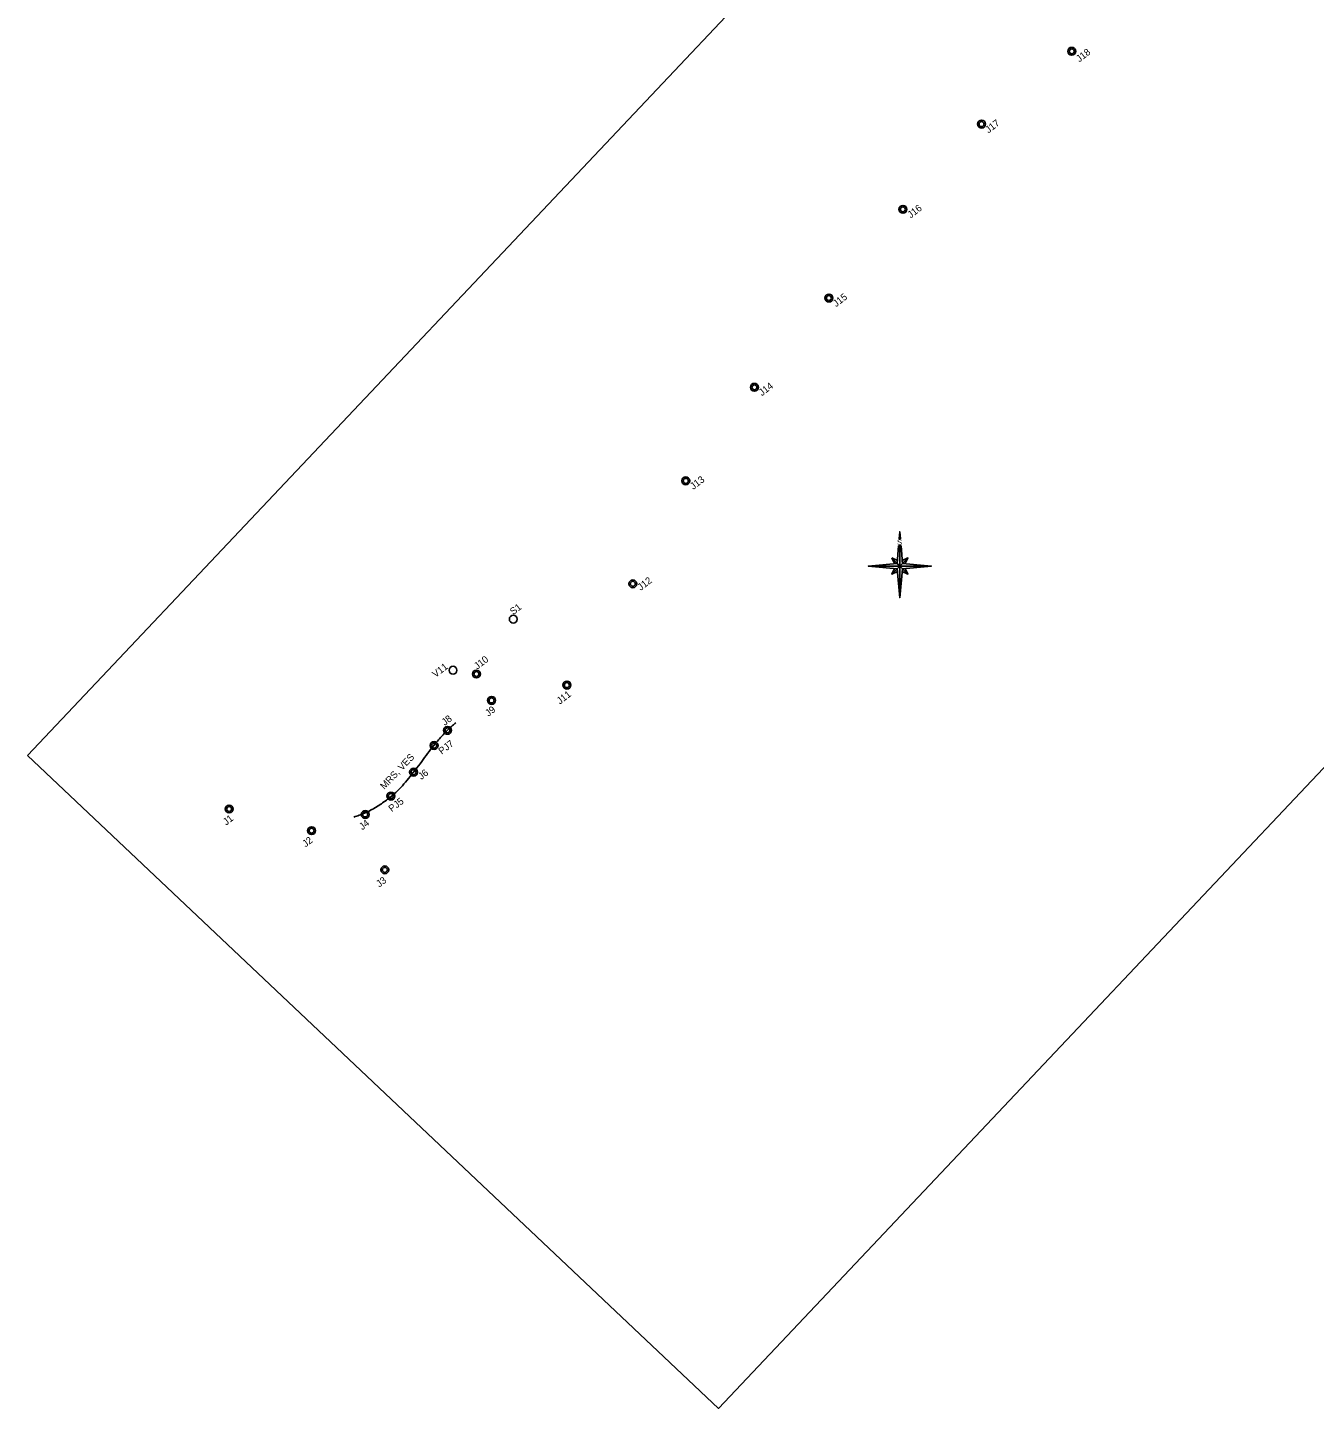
# Model space of a CAD drawing. Extents: x -705558 to -700007, y -1016452 to -1010613.
# Drawn here: x -705558 to -702782, y -1016452 to -1013474 of the extents above; entities that cross this region are included whole.
import ezdxf

# ---------------------------------------------------------------- set-up
doc = ezdxf.new("R2010")
doc.units = 0
for name, color, linetype in [('arch_vrty', 7, 'Continuous'), ('geofyzika', 7, 'Continuous'), ('rozpiska', 7, 'Continuous'), ('vrty', 7, 'Continuous'), ('vrty_popis', 7, 'Continuous')]:
    doc.layers.add(name, color=color, linetype=linetype)

msp = doc.modelspace()

# ---------------------------------------------------------------- linework, layer by layer
at = {"layer": 'arch_vrty'}
for centre in [(-704510, -1014750), (-704640, -1014860)]:
    msp.add_circle(centre, 8.53, dxfattribs=at)
at = {"layer": 'geofyzika'}
msp.add_spline([(-704854, -1015176.8), (-704830.6, -1015168.1), (-704805.6, -1015155), (-704783.8, -1015140.1), (-704763.5, -1015123.7), (-704735.9, -1015093.4), (-704707.6, -1015056.9), (-704681.7, -1015022.7), (-704665, -1015002.9), (-704651, -1014988.3), (-704640.9, -1014979), (-704634.2, -1014973.4)], degree=3, dxfattribs=at)
at = {"layer": 'rozpiska'}
for p, q in [((-703677.6, -1014576.4), (-703676.3, -1014561.4)), ((-703677.6, -1014576.4), (-703675, -1014576.4)), ((-703676.3, -1014561.4), (-703676.3, -1014576.4)), ((-703675, -1014576.4), (-703676.3, -1014561.4)), ((-703693.8, -1014617.9), (-703682.1, -1014629.6)), ((-703693.8, -1014617.9), (-703681.6, -1014623.6)), ((-703693.8, -1014617.9), (-703688.1, -1014630.1)), ((-703682.1, -1014629.6), (-703678.9, -1014591.9)), ((-703673.7, -1014591.9), (-703678.9, -1014591.9)), ((-703676.3, -1014591.9), (-703676.3, -1014628.8)), ((-703676.3, -1014591.9), (-703676.3, -1014635.4)), ((-703670.5, -1014629.6), (-703673.7, -1014591.9)), ((-703658.8, -1014617.9), (-703671, -1014623.6)), ((-703658.8, -1014617.9), (-703670.5, -1014629.6)), ((-703658.8, -1014617.9), (-703664.5, -1014630.1)), ((-703682.1, -1014629.6), (-703744.5, -1014635.4)), ((-703744.5, -1014635.4), (-703682.9, -1014635.4)), ((-703682.1, -1014641.2), (-703744.5, -1014635.4)), ((-703693.8, -1014652.9), (-703688.1, -1014640.7)), ((-703693.8, -1014652.9), (-703682.1, -1014641.2)), ((-703693.8, -1014652.9), (-703681.6, -1014647.2)), ((-703682.9, -1014635.4), (-703676.3, -1014635.4)), ((-703682.1, -1014629.6), (-703670.5, -1014641.2)), ((-703676.3, -1014635.4), (-703682.1, -1014641.2)), ((-703682.1, -1014641.2), (-703676.3, -1014703.6)), ((-703676.3, -1014628.8), (-703676.3, -1014635.4)), ((-703670.5, -1014629.6), (-703676.3, -1014635.4)), ((-703669.7, -1014635.4), (-703676.3, -1014635.4)), ((-703676.3, -1014642), (-703676.3, -1014635.4)), ((-703670.5, -1014641.2), (-703676.3, -1014703.6)), ((-703676.3, -1014703.6), (-703676.3, -1014642)), ((-703658.8, -1014652.9), (-703671, -1014647.2)), ((-703670.5, -1014629.6), (-703608.1, -1014635.4)), ((-703670.5, -1014641.2), (-703608.1, -1014635.4)), ((-703658.8, -1014652.9), (-703670.5, -1014641.2)), ((-703608.1, -1014635.4), (-703669.7, -1014635.4)), ((-703658.8, -1014652.9), (-703664.5, -1014640.7))]:
    msp.add_line(p, q, dxfattribs=at)
msp.add_lwpolyline([(-705557.6, -1015043.6), (-701496.6, -1010746.7), (-700006.7, -1012154.8), (-704067.7, -1016451.7)], close=True, dxfattribs=at)
for points in [[(-703676.3, -1014576.4), (-703676.3, -1014561.4), (-703677.6, -1014576.4), (-703676.3, -1014576.4)], [(-703693.8, -1014617.9), (-703688.1, -1014630.1), (-703682.1, -1014629.6), (-703693.8, -1014617.9)], [(-703678.9, -1014591.9), (-703682.1, -1014629.6), (-703676.5, -1014635.2), (-703676.3, -1014635.2), (-703676.3, -1014591.9), (-703678.9, -1014591.9)], [(-703671, -1014623.6), (-703670.5, -1014629.6), (-703658.8, -1014617.9), (-703671, -1014623.6)], [(-703682.1, -1014641.2), (-703676.3, -1014635.4), (-703682.9, -1014635.4), (-703744.5, -1014635.4), (-703682.1, -1014641.2)], [(-703682.1, -1014641.2), (-703693.8, -1014652.9), (-703681.6, -1014647.2), (-703682.1, -1014641.2)], [(-703676.3, -1014635.4), (-703676.3, -1014635.4), (-703676.3, -1014635.4), (-703676.3, -1014635.4), (-703669.7, -1014635.4), (-703608.1, -1014635.4), (-703670.5, -1014629.6), (-703676.3, -1014635.4)], [(-703670.5, -1014641.2), (-703676.3, -1014635.4), (-703676.3, -1014635.4), (-703676.3, -1014642), (-703676.3, -1014703.6), (-703670.5, -1014641.2)], [(-703664.5, -1014640.7), (-703670.5, -1014641.2), (-703658.8, -1014652.9), (-703664.5, -1014640.7)]]:
    msp.add_lwpolyline(points, dxfattribs=at)
at = {"layer": 'vrty'}
for centre, radius in [((-703305.4, -1013525.5), 8.53), ((-703305.4, -1013525.5), 5.37), ((-703500, -1013682.5), 8.53), ((-703500, -1013682.5), 5.37), ((-703669.7, -1013866.2), 8.53), ((-703669.7, -1013866.2), 5.37), ((-703829.3, -1014057.5), 8.53), ((-703829.3, -1014057.5), 5.37), ((-703989.9, -1014250), 8.53), ((-703989.9, -1014250), 5.37), ((-704138.1, -1014451.7), 8.53), ((-704138.1, -1014451.7), 5.37), ((-704252.2, -1014673.7), 8.53), ((-704252.2, -1014673.7), 5.37), ((-704589.6, -1014868.2), 8.53), ((-704589.6, -1014868.2), 5.37), ((-704394.4, -1014892), 8.53), ((-704394.4, -1014892), 5.37), ((-704556.8, -1014925.1), 8.53), ((-704556.8, -1014925.1), 5.37), ((-704651.9, -1014989.7), 8.53), ((-704651.9, -1014989.7), 5.37), ((-704680.8, -1015022.4), 8.53), ((-704680.8, -1015022.4), 5.37), ((-704725, -1015079.9), 8.53), ((-704725, -1015079.9), 5.37), ((-704773.9, -1015131.5), 8.53), ((-705122.9, -1015159.3), 8.53), ((-705122.9, -1015159.3), 5.37), ((-704773.9, -1015131.5), 5.37), ((-704829.3, -1015171.1), 8.53), ((-704829.3, -1015171.1), 5.37), ((-704945, -1015206), 8.53), ((-704945, -1015206), 5.37), ((-704787, -1015290.5), 8.53), ((-704787, -1015290.5), 5.37)]:
    msp.add_circle(centre, radius, dxfattribs=at)

# ---------------------------------------------------------------- texts
at = {"layer": 'arch_vrty'}
for s, p in [('S1', (-704510.2, -1014741.6)), ('V11', (-704677.8, -1014876.8))]:
    msp.add_text(s, height=15, rotation=37.475, dxfattribs=at).set_placement(p)
at = {"layer": 'geofyzika'}
msp.add_text('MRS, VES', height=15, rotation=46.6172, dxfattribs=at).set_placement((-704788, -1015118.1))
at = {"layer": 'rozpiska'}
msp.add_text('S', height=11.8, rotation=359.9916, dxfattribs=at).set_placement((-703682.3, -1014589.8))
at = {"layer": 'vrty_popis'}
for s, p in [('J18', (-703289.2, -1013549.7)), ('J17', (-703485.1, -1013702.9)), ('J16', (-703652.8, -1013886.2)), ('J15', (-703813.8, -1014077.6)), ('J14', (-703973.6, -1014269.5)), ('J13', (-704121.7, -1014471.4)), ('J12', (-704235.1, -1014689.1)), ('J10', (-704587.7, -1014859.2)), ('J11', (-704409.4, -1014934.3)), ('J9', (-704563.7, -1014960.6)), ('J8', (-704657.6, -1014980.2)), ('PJ7', (-704664.3, -1015042.4)), ('J6', (-704708.4, -1015096.9)), ('PJ5', (-704772.1, -1015166.4)), ('J1', (-705129.2, -1015195.2)), ('J4', (-704835.6, -1015205.4)), ('J2', (-704958, -1015242.4)), ('J3', (-704798.8, -1015328.8))]:
    msp.add_text(s, height=15, rotation=37.475, dxfattribs=at).set_placement(p)

doc.saveas('drawing.dxf')
